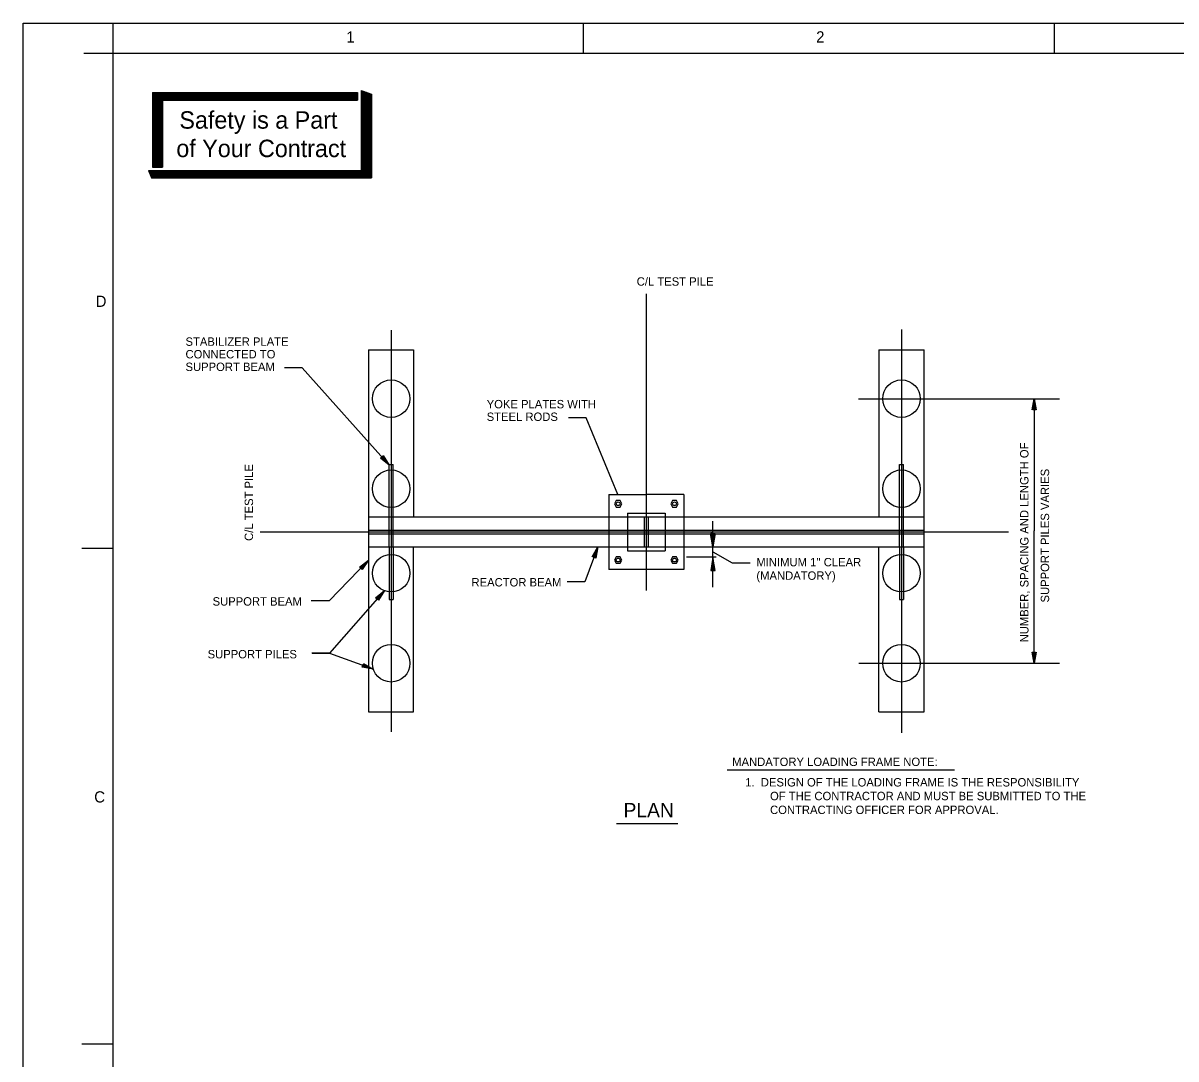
# Model space of a CAD drawing. Extents: x 22369.6 to 22413.6, y 22369.6 to 22403.6.
# Drawn here: x 22369.62 to 22388.82, y 22386.37 to 22403.63 of the extents above; entities that cross this region are included whole.
import ezdxf

# ---------------------------------------------------------------- set-up
doc = ezdxf.new("R2010")
doc.units = 0
for name, color, linetype in [('Level 1', 7, 'Continuous'), ('Level 10', 7, 'Continuous'), ('Level 2', 7, 'Continuous'), ('Level 3', 7, 'Continuous'), ('Level 4', 7, 'Continuous'), ('Level 7', 7, 'Continuous'), ('Level 9', 7, 'Continuous')]:
    doc.layers.add(name, color=color, linetype=linetype)

msp = doc.modelspace()

# ---------------------------------------------------------------- linework, layer by layer
at = {"layer": 'Level 1'}
for p, q in [((22380.002, 22399.121), (22380.002, 22394.179)), ((22375.752, 22398.514), (22375.752, 22391.82)), ((22384.252, 22398.527), (22384.252, 22391.805)), ((22383.536, 22397.372), (22386.884, 22397.372)), ((22386.462, 22397.372), (22386.462, 22395.168)), ((22386.462, 22397.372), (22386.462, 22397.372)), ((22386.462, 22397.32), (22386.462, 22397.32)), ((22375.686, 22396.303), (22375.686, 22396.303)), ((22375.721, 22396.265), (22375.721, 22396.265)), ((22379.502, 22395.676), (22379.471, 22395.622)), ((22379.471, 22395.622), (22379.502, 22395.567)), ((22379.564, 22395.676), (22379.502, 22395.676)), ((22379.596, 22395.622), (22379.564, 22395.676)), ((22379.564, 22395.567), (22379.596, 22395.622)), ((22380.439, 22395.676), (22380.408, 22395.622)), ((22380.408, 22395.622), (22380.439, 22395.567)), ((22380.502, 22395.676), (22380.439, 22395.676)), ((22380.533, 22395.622), (22380.502, 22395.676)), ((22380.502, 22395.567), (22380.533, 22395.622)), ((22379.502, 22395.567), (22379.564, 22395.567)), ((22380.439, 22395.567), (22380.502, 22395.567)), ((22381.111, 22394.231), (22381.111, 22395.331)), ((22373.571, 22395.153), (22386.032, 22395.153)), ((22381.073, 22395.128), (22381.148, 22395.128)), ((22381.111, 22394.903), (22381.073, 22395.128)), ((22381.107, 22395.124), (22381.078, 22395.124)), ((22381.078, 22395.124), (22381.107, 22394.949)), ((22381.107, 22395.12), (22381.084, 22395.12)), ((22381.084, 22395.12), (22381.103, 22394.992)), ((22381.103, 22395.115), (22381.089, 22395.115)), ((22381.089, 22395.115), (22381.098, 22395.051)), ((22381.098, 22395.051), (22381.097, 22395.111)), ((22381.103, 22394.992), (22381.103, 22395.115)), ((22381.107, 22394.949), (22381.107, 22395.12)), ((22381.111, 22394.903), (22381.111, 22395.128)), ((22381.148, 22395.128), (22381.111, 22394.903)), ((22381.143, 22395.124), (22381.114, 22394.949)), ((22381.114, 22394.949), (22381.115, 22395.119)), ((22381.115, 22395.124), (22381.143, 22395.124)), ((22381.115, 22395.119), (22381.138, 22395.119)), ((22381.138, 22395.119), (22381.118, 22394.992)), ((22381.118, 22394.992), (22381.119, 22395.115)), ((22381.119, 22395.115), (22381.132, 22395.115)), ((22381.132, 22395.115), (22381.122, 22395.051)), ((22381.122, 22395.051), (22381.123, 22395.111)), ((22386.462, 22392.965), (22386.462, 22395.168)), ((22379.178, 22394.854), (22379.178, 22394.854)), ((22379.197, 22394.903), (22379.197, 22394.903)), ((22375.377, 22394.68), (22375.377, 22394.68)), ((22379.502, 22394.738), (22379.471, 22394.684)), ((22379.471, 22394.684), (22379.502, 22394.63)), ((22379.564, 22394.738), (22379.502, 22394.738)), ((22379.596, 22394.684), (22379.564, 22394.738)), ((22379.564, 22394.63), (22379.596, 22394.684)), ((22380.439, 22394.738), (22380.408, 22394.684)), ((22380.408, 22394.684), (22380.439, 22394.63)), ((22380.502, 22394.738), (22380.439, 22394.738)), ((22380.533, 22394.684), (22380.502, 22394.738)), ((22380.502, 22394.63), (22380.533, 22394.684)), ((22380.669, 22394.737), (22381.165, 22394.737)), ((22381.112, 22394.733), (22381.075, 22394.509)), ((22381.08, 22394.512), (22381.109, 22394.687)), ((22381.109, 22394.687), (22381.109, 22394.517)), ((22381.112, 22394.733), (22381.112, 22394.509)), ((22381.15, 22394.509), (22381.112, 22394.733)), ((22381.145, 22394.513), (22381.116, 22394.688)), ((22381.116, 22394.688), (22381.116, 22394.517)), ((22375.34, 22394.643), (22375.34, 22394.643)), ((22379.502, 22394.63), (22379.564, 22394.63)), ((22380.439, 22394.63), (22380.502, 22394.63)), ((22381.075, 22394.509), (22381.15, 22394.509)), ((22381.109, 22394.512), (22381.08, 22394.512)), ((22381.085, 22394.516), (22381.105, 22394.644)), ((22381.109, 22394.517), (22381.085, 22394.516)), ((22381.091, 22394.521), (22381.1, 22394.586)), ((22381.104, 22394.522), (22381.091, 22394.521)), ((22381.1, 22394.586), (22381.099, 22394.525)), ((22381.105, 22394.644), (22381.104, 22394.522)), ((22381.116, 22394.517), (22381.139, 22394.518)), ((22381.116, 22394.512), (22381.145, 22394.513)), ((22381.139, 22394.518), (22381.119, 22394.645)), ((22381.119, 22394.645), (22381.121, 22394.522)), ((22381.121, 22394.522), (22381.134, 22394.522)), ((22381.134, 22394.522), (22381.124, 22394.585)), ((22381.124, 22394.585), (22381.125, 22394.525)), ((22375.605, 22394.135), (22375.605, 22394.135)), ((22375.639, 22394.174), (22375.639, 22394.174)), ((22383.542, 22392.965), (22386.881, 22392.965)), ((22386.462, 22393.017), (22386.462, 22393.017)), ((22386.462, 22392.965), (22386.462, 22392.965)), ((22375.406, 22392.885), (22375.406, 22392.885)), ((22375.455, 22392.867), (22375.455, 22392.867))]:
    msp.add_line(p, q, dxfattribs=at)
msp.add_lwpolyline([(22369.621, 22403.629), (22413.622, 22403.629), (22413.622, 22369.621), (22369.621, 22369.621)], close=True, dxfattribs=at)
for points in [[(22375.721, 22396.265), (22374.271, 22397.885), (22373.975, 22397.885)], [(22386.431, 22397.185), (22386.462, 22397.372), (22386.493, 22397.185), (22386.44, 22397.185), (22386.462, 22397.32), (22386.483, 22397.193), (22386.449, 22397.193), (22386.462, 22397.27), (22386.473, 22397.201), (22386.459, 22397.201), (22386.462, 22397.218)], [(22379.527, 22395.778), (22379, 22397.054), (22378.704, 22397.054)], [(22375.619, 22396.425), (22375.721, 22396.265), (22375.573, 22396.383), (22375.612, 22396.419), (22375.686, 22396.303), (22375.586, 22396.384), (22375.611, 22396.407), (22375.653, 22396.341), (22375.598, 22396.385), (22375.609, 22396.394), (22375.618, 22396.379)], [(22379.197, 22394.903), (22378.977, 22394.32), (22378.681, 22394.32)], [(22379.102, 22394.739), (22379.197, 22394.903), (22379.16, 22394.717), (22379.11, 22394.736), (22379.178, 22394.854), (22379.153, 22394.728), (22379.121, 22394.74), (22379.161, 22394.807), (22379.147, 22394.739), (22379.134, 22394.744), (22379.142, 22394.759)], [(22375.377, 22394.68), (22374.717, 22394.007), (22374.421, 22394.007)], [(22375.224, 22394.568), (22375.377, 22394.68), (22375.268, 22394.525), (22375.23, 22394.562), (22375.34, 22394.643), (22375.267, 22394.538), (22375.242, 22394.561), (22375.305, 22394.607), (22375.265, 22394.55), (22375.255, 22394.56), (22375.269, 22394.57)], [(22381.111, 22394.821), (22381.432, 22394.638), (22381.729, 22394.638)], [(22375.639, 22394.174), (22374.726, 22393.133), (22374.429, 22393.133)], [(22375.492, 22394.054), (22375.639, 22394.174), (22375.539, 22394.013), (22375.499, 22394.048), (22375.605, 22394.135), (22375.537, 22394.025), (22375.511, 22394.048), (22375.572, 22394.097), (22375.535, 22394.038), (22375.524, 22394.047), (22375.537, 22394.058)], [(22375.455, 22392.867), (22374.731, 22393.129), (22374.435, 22393.129)], [(22386.493, 22393.152), (22386.462, 22392.965), (22386.431, 22393.152), (22386.484, 22393.152), (22386.462, 22393.017), (22386.441, 22393.144), (22386.475, 22393.144), (22386.462, 22393.067), (22386.451, 22393.136), (22386.465, 22393.136), (22386.462, 22393.119)]]:
    msp.add_lwpolyline(points, dxfattribs=at)
for centre in [(22379.533, 22395.622), (22380.471, 22395.622), (22379.533, 22394.684), (22380.471, 22394.684)]:
    msp.add_ellipse(centre, major_axis=(0.0313, 0), ratio=0.999667, dxfattribs=at)
at = {"layer": 'Level 10'}
for p, q in [((22371.121, 22403.125), (22371.121, 22403.629)), ((22378.954, 22403.125), (22378.954, 22403.629)), ((22386.802, 22403.125), (22386.802, 22403.629)), ((22370.633, 22403.125), (22371.116, 22403.125)), ((22371.775, 22402.471), (22375.192, 22402.471)), ((22371.775, 22402.471), (22371.775, 22401.23)), ((22371.775, 22402.455), (22375.192, 22402.455)), ((22371.775, 22402.44), (22375.192, 22402.44)), ((22371.775, 22402.424), (22375.192, 22402.424)), ((22371.775, 22402.408), (22375.192, 22402.408)), ((22371.775, 22402.393), (22375.192, 22402.393)), ((22371.775, 22402.377), (22375.192, 22402.377)), ((22371.775, 22402.362), (22375.192, 22402.362)), ((22371.791, 22402.471), (22371.791, 22401.23)), ((22371.806, 22402.471), (22371.806, 22401.23)), ((22371.822, 22402.471), (22371.822, 22401.23)), ((22371.837, 22402.471), (22371.837, 22401.23)), ((22371.853, 22402.471), (22371.853, 22401.23)), ((22371.869, 22402.471), (22371.869, 22401.23)), ((22371.884, 22402.471), (22371.884, 22401.23)), ((22371.9, 22402.471), (22371.9, 22401.23)), ((22371.916, 22402.471), (22371.916, 22401.23)), ((22371.931, 22402.471), (22371.931, 22401.23)), ((22371.942, 22402.346), (22375.192, 22402.346)), ((22371.942, 22402.346), (22371.942, 22401.23)), ((22375.192, 22402.471), (22375.192, 22402.346)), ((22375.255, 22402.508), (22375.255, 22401.174)), ((22375.255, 22402.508), (22375.422, 22402.446)), ((22375.266, 22402.504), (22375.266, 22401.049)), ((22375.281, 22402.498), (22375.281, 22401.049)), ((22375.297, 22402.492), (22375.297, 22401.049)), ((22375.313, 22402.486), (22375.313, 22401.049)), ((22375.328, 22402.481), (22375.328, 22401.049)), ((22375.344, 22402.475), (22375.344, 22401.049)), ((22375.359, 22402.469), (22375.359, 22401.049)), ((22375.375, 22402.463), (22375.375, 22401.049)), ((22375.391, 22402.458), (22375.391, 22401.049)), ((22375.406, 22402.446), (22375.406, 22401.049)), ((22375.422, 22402.446), (22375.422, 22401.049)), ((22371.775, 22401.23), (22371.942, 22401.23)), ((22371.712, 22401.174), (22375.255, 22401.174)), ((22371.712, 22401.174), (22371.758, 22401.049)), ((22371.718, 22401.158), (22375.266, 22401.158)), ((22371.723, 22401.143), (22375.266, 22401.143)), ((22371.729, 22401.127), (22375.266, 22401.127)), ((22371.735, 22401.111), (22375.266, 22401.111)), ((22371.741, 22401.096), (22375.266, 22401.096)), ((22371.747, 22401.08), (22375.266, 22401.08)), ((22371.752, 22401.065), (22375.266, 22401.065)), ((22371.758, 22401.049), (22375.422, 22401.049)), ((22370.602, 22394.881), (22371.106, 22394.881)), ((22379.507, 22390.297), (22380.527, 22390.297)), ((22370.602, 22386.625), (22371.106, 22386.625))]:
    msp.add_line(p, q, dxfattribs=at)
at = {"layer": 'Level 2'}
for p, q in [((22375.721, 22396.278), (22375.783, 22396.278)), ((22375.721, 22395.403), (22375.721, 22396.278)), ((22375.783, 22395.403), (22375.783, 22396.278)), ((22384.221, 22395.403), (22384.221, 22396.278)), ((22384.221, 22396.278), (22384.283, 22396.278)), ((22384.283, 22395.403), (22384.283, 22396.278)), ((22379.689, 22395.465), (22380.314, 22395.465)), ((22379.689, 22395.465), (22379.689, 22394.84)), ((22380.314, 22395.465), (22380.314, 22394.84)), ((22375.721, 22394.903), (22375.721, 22395.403)), ((22375.783, 22394.903), (22375.783, 22395.403)), ((22379.377, 22395.403), (22380.002, 22395.403)), ((22379.971, 22394.903), (22379.971, 22395.403)), ((22380.002, 22395.403), (22380.627, 22395.403)), ((22380.033, 22395.403), (22380.033, 22394.903)), ((22384.221, 22394.903), (22384.221, 22395.403)), ((22384.283, 22394.903), (22384.283, 22395.403)), ((22375.377, 22395.184), (22384.627, 22395.184)), ((22375.377, 22395.122), (22384.627, 22395.122)), ((22375.721, 22394.903), (22375.721, 22394.028)), ((22375.783, 22394.903), (22375.783, 22394.028)), ((22379.377, 22394.903), (22380.002, 22394.903)), ((22379.689, 22394.84), (22380.314, 22394.84)), ((22380.002, 22394.903), (22380.627, 22394.903)), ((22384.221, 22394.903), (22384.221, 22394.028)), ((22384.283, 22394.903), (22384.283, 22394.028)), ((22375.721, 22394.028), (22375.783, 22394.028)), ((22384.221, 22394.028), (22384.283, 22394.028))]:
    msp.add_line(p, q, dxfattribs=at)
msp.add_lwpolyline([(22375.29, 22392.96), (22375.455, 22392.867), (22375.269, 22392.901), (22375.287, 22392.951), (22375.406, 22392.885), (22375.28, 22392.908), (22375.291, 22392.94), (22375.359, 22392.902), (22375.291, 22392.915), (22375.295, 22392.928), (22375.31, 22392.919)], dxfattribs=at)
for centre in [(22375.752, 22397.372), (22384.252, 22397.372), (22375.752, 22395.872), (22384.252, 22395.872), (22375.752, 22394.465), (22384.252, 22394.465), (22375.752, 22392.965), (22384.252, 22392.965)]:
    msp.add_circle(centre, 0.313, dxfattribs=at)
at = {"layer": 'Level 7'}
for p, q in [((22375.377, 22398.184), (22376.127, 22398.184)), ((22375.377, 22398.184), (22375.377, 22392.153)), ((22376.127, 22398.184), (22376.127, 22395.403)), ((22383.877, 22398.184), (22384.627, 22398.184)), ((22383.877, 22398.184), (22383.877, 22395.403)), ((22384.627, 22392.153), (22384.627, 22398.184)), ((22379.377, 22395.778), (22379.377, 22394.528)), ((22379.377, 22395.778), (22380.002, 22395.778)), ((22380.627, 22395.778), (22380.002, 22395.778)), ((22380.627, 22395.778), (22380.627, 22394.528)), ((22375.377, 22395.403), (22379.377, 22395.403)), ((22380.627, 22395.403), (22384.627, 22395.403)), ((22375.377, 22394.903), (22379.377, 22394.903)), ((22376.127, 22392.153), (22376.127, 22394.903)), ((22380.627, 22394.903), (22384.627, 22394.903)), ((22383.877, 22392.153), (22383.877, 22394.903)), ((22380.002, 22394.528), (22379.377, 22394.528)), ((22380.627, 22394.528), (22380.002, 22394.528)), ((22375.377, 22392.153), (22376.127, 22392.153)), ((22383.877, 22392.153), (22384.627, 22392.153)), ((22381.348, 22391.188), (22385.135, 22391.188))]:
    msp.add_line(p, q, dxfattribs=at)
at = {"layer": 'Level 9'}
for p, q in [((22371.121, 22370.125), (22371.121, 22403.125)), ((22371.121, 22403.125), (22410.37, 22403.125))]:
    msp.add_line(p, q, dxfattribs=at)

# ---------------------------------------------------------------- texts
at = {"layer": 'Level 1'}
for s, p in [('1', (22375.006, 22403.305)), ('2', (22382.83, 22403.305)), ('D', (22370.83, 22398.901)), ('C', (22370.806, 22390.645))]:
    msp.add_text(s, height=0.187, dxfattribs=at).set_placement(p)
at = {"layer": 'Level 10'}
for s, p in [('Safety is a Part', (22372.225, 22401.87)), ('of Your Contract', (22372.174, 22401.396))]:
    msp.add_text(s, height=0.29038, dxfattribs=at).set_placement(p)
at = {"layer": 'Level 3'}
msp.add_text('PLAN', height=0.24, dxfattribs=at).set_placement((22379.622, 22390.398))
at = {"layer": 'Level 4'}
for s, p in [('C/L TEST PILE', (22379.842, 22399.254)), ('STABILIZER PLATE', (22372.327, 22398.253)), ('CONNECTED TO', (22372.327, 22398.043)), ('SUPPORT BEAM', (22372.327, 22397.833)), ('YOKE PLATES WITH', (22377.343, 22397.211)), ('STEEL RODS', (22377.343, 22397.001)), ('REACTOR BEAM', (22377.09, 22394.244)), ('SUPPORT BEAM', (22372.778, 22393.925)), ('SUPPORT PILES', (22372.695, 22393.046)), ('MANDATORY LOADING FRAME NOTE:', (22381.432, 22391.253)), ('1.  DESIGN OF THE LOADING FRAME IS THE RESPONSIBILITY ', (22381.649, 22390.912)), ('OF THE CONTRACTOR AND MUST BE SUBMITTED TO THE', (22382.063, 22390.683)), ('CONTRACTING OFFICER FOR APPROVAL.', (22382.063, 22390.453))]:
    msp.add_text(s, height=0.14, dxfattribs=at).set_placement(p)
for s, p in [('NUMBER, SPACING AND LENGTH OF', (22386.367, 22393.313)), ('C/L TEST PILE', (22373.452, 22395.003)), ('SUPPORT PILES VARIES', (22386.711, 22393.977))]:
    msp.add_text(s, height=0.14, rotation=90, dxfattribs=at).set_placement(p)
at = {"layer": 'Level 7'}
for s, p in [("MINIMUM 1'' CLEAR", (22381.835, 22394.579)), ('(MANDATORY)', (22381.835, 22394.355))]:
    msp.add_text(s, height=0.14, dxfattribs=at).set_placement(p)

doc.saveas('drawing.dxf')
